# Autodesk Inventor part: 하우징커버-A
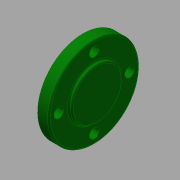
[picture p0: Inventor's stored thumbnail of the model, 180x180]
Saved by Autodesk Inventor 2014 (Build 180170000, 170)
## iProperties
Created: 2018-01
Part Number: 하우징커버-A
Material: 알루미늄 6061
Document SubType Name: Modeling
Designer: mduedu
Density: 2.71 g/cm^3
Appearance: 진녹색
Mass: 8.99967 g
Surface Area: 21.1948 cm^2
Volume: 3.32091 cm^3
Author: mduedu
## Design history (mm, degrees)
sketch "스케치1"
  geometry: C1 r 16 at (0, 0); 1 further point
  constraints: 1 centre point, 1 coincident
  dimensions: "d0" = 32 diameter of C1
extrude "돌출1" new body sketch "스케치1" distance "d1" = 4; taper "d2" = 0 deg
sketch "스케치2"
  geometry: C1 r 9 at (0, 0); 1 further point
  constraints: 1 centre point, 1 coincident
  dimensions: "d3" = 18 diameter of C1
extrude "돌출2" join sketch "스케치2" distance "d4" = 1; taper "d5" = 0 deg
fillet "모깎기1" dims "d6" = 0.5
fillet "모깎기2" dims "d7" = 0.5
sketch "스케치3" dims "d8" = 25
  geometry: 6 further points
  constraints: 2 vertical alignment, 1 coincident, 7 other
  dimensions: "d11" = 360 deg dimension on point (0, 0) point (0, 12.5) (derived)
sketch "스케치4"
  geometry: 4 further points
  constraints: 4 other
hole "구멍1" sketch "스케치4" at (-12.5, 0), (0, -12.5), (12.5, 0), (0, 12.5) diameter "d13" = 3.4; stored, may be unused: countersink angle "d17" = 90 deg, drill point angle "d19" = 0 deg; dims "d14" = 6, "d15" = 4, "d16" = 2, "d18" = 8
node "솔리드1"
